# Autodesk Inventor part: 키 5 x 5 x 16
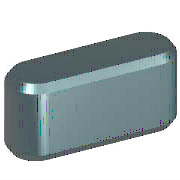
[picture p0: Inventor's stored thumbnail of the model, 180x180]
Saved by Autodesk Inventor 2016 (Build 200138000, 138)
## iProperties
IsCustomPart: 1
Created: 2012-02
Part Number: 키 5 x 5 x 16
Material: 강철, 연강
Description: 키 및 해당 키홈
Document SubType Name: Modeling
Standard: KS B 1311
Designer: mduedu
Standards Organization: KS
Language: ko-KR
Size Designation: 5 x 5 x 16
Categories: <MemberInstance><Categories><Category DisplayName="샤프트 부품" InternalName="7f7aeb1f-a693-4053-b835-cee3144e0d98" Mnemonic="SHFT"><Category DisplayName="키" Interna
Density: 7.85 g/cm^3
Appearance: 노란색
Mass: 2.88311 g
Surface Area: 3.19722 cm^2
Volume: 0.367276 cm^3
Author: mduedu
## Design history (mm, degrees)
workplane "Work Plane1"
workplane "Work Plane2"
sketch "스케치1"
  geometry: L1 (2.5, 2.5)-(13.5, 2.5); L2 (13.5, -2.5)-(2.5, -2.5); L3 (0, 9.4)-(0, -7.4) reference; L4 (-5, 0)-(30, 0) reference; L5 (16, 0)-(16, 7); A1 r 2.5 centre (2.5, 0) between (2.5, 2.5) and (2.5, -2.5); A2 r 2.5 centre (13.5, 0) between (13.5, -2.5) and (13.5, 2.5)
  constraints: 6 end point, 5 point on circle, 4 tangent, 3 point on line, 2 centre point, 1 horizontal, 1 parallel, 1 perpendicular
  dimensions: "d0" = 2.5 radius of A1 (= 0.5 x PB); "d13" = 2.5 radius of A2 (= 0.5 x PB); "d14" = 16 distance between parallel lines of L5 L3 (= NLG)
extrude "본체1" new body sketch "스케치1" taper "d3" = 0 deg; stored distance "d4" = 10
workplane "Work Plane3"
body "Solid1"
chamfer "모따기1" distance "d8" = 0.4 (= PHH); stored, may be unused: second distance "d9" = 0.4 (= PHH), angle "d15" = 45 deg
other parameters: "d1" = -3 (= -PNT), "d2" = 2 (= PH - PNT), "NLG" = 16 [user parameter; used in 3 equation terms], "PB" = 5 [user parameter; used in 2 equation terms], "PNT" = 3 [user parameter; used in 2 equation terms], "PH" = 5 [user parameter; used in 1 equation term], "PHH" = 0.4 [user parameter; used in 2 equation terms], "d10" = 0, "d16" = 0, "d17" = 0, "d18" = 0, "WDMIN" = 12 [user parameter], "PLB2" = 16 (= NLG) [user parameter], "WDMAX" = 17 [user parameter], "PLB1" = 16 (= NLG) [user parameter], "RR" = 0.16 [user parameter], "PUEB" = 2.3 [user parameter]
